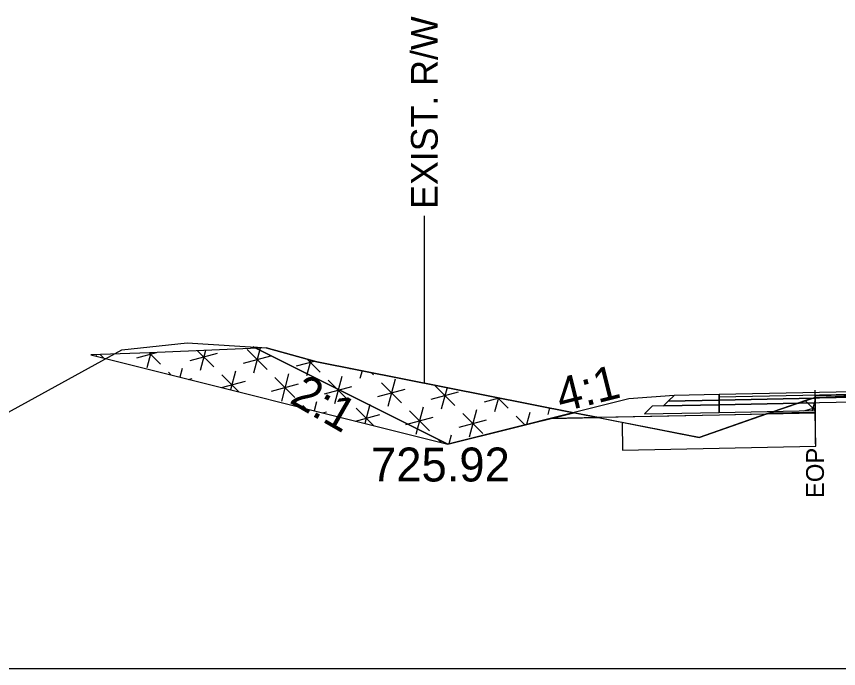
# Model space of a CAD drawing. Extents: x -26 to 4303, y -10 to 9577.
# Drawn here: x 4101.93 to 4138.27, y 2500 to 2528.83 of the extents above; entities that cross this region are included whole.
import ezdxf

# ---------------------------------------------------------------- set-up
doc = ezdxf.new("R2010")
doc.units = 0
for name, color, linetype in [('Exist CMT Pavement', 7, 'Continuous'), ('Old_Level_2', 7, 'Continuous'), ('Pattern 3', 7, 'Continuous'), ('Prop CMT Conc Surface', 7, 'Continuous'), ('Prop CMT Concrete Structures', 7, 'Continuous'), ('Prop CMT Pvmt Course 1', 7, 'Continuous'), ('Prop CMT Pvmt Course 2', 7, 'Continuous'), ('Prop CMT Pvmt Course 2 Wedge', 7, 'Continuous'), ('Prop CMT Pvmt Course 3', 7, 'Continuous'), ('Prop CMT Pvmt Surface', 7, 'Continuous'), ('Prop CMT Pvmt Surface Shoulder', 7, 'Continuous'), ('Prop CMT Pvmt Wedge Surface 1', 7, 'Continuous'), ('Prop CMT Pvmt Wedge Surface 2', 7, 'Continuous'), ('Prop CMT Shld Paved Course 1', 7, 'Continuous'), ('Prop CMT Shld Paved Course 2', 7, 'Continuous'), ('Prop CMT Shld Paved Course 3', 7, 'Continuous'), ('Prop CMT Slope Grass', 7, 'Continuous'), ('Prop CMT Subgrade Earthwork', 7, 'Continuous'), ('Prop Road Sect_ Recs - UC Shallow (Outline)', 7, 'Continuous'), ('Prop Shade Light', 7, 'Continuous'), ('Prop XS DDE Elevations', 7, 'Continuous'), ('Prop XS Ditch Standard Text', 7, 'Continuous'), ('Prop XS Hydro Elevations', 7, 'Continuous'), ('Prop XS Side Slope Text', 7, 'Continuous'), ('Prop XS Wedging', 7, 'Continuous')]:
    doc.layers.add(name, color=color, linetype=linetype)

msp = doc.modelspace()

# ---------------------------------------------------------------- linework, layer by layer
at = {"layer": 'Exist CMT Pavement'}
msp.add_lwpolyline([(4150, 2512.457), (4133, 2512.117)], dxfattribs=at)
at = {"layer": 'Old_Level_2'}
msp.add_line((4000, 2500), (4150, 2500), dxfattribs=at)
msp.add_line((4000, 2500), (4150, 2500), dxfattribs=at)
at = {"layer": 'Pattern 3'}
for p, q in [((4107.248, 2513.735), (4108.115, 2513.968)), ((4107.868, 2513.957), (4107.69, 2513.294)), ((4107.795, 2513.954), (4108.294, 2513.455)), ((4109.605, 2513.617), (4110.812, 2513.941)), ((4109.939, 2514.048), (4110.65, 2513.337)), ((4110.285, 2514.064), (4110.047, 2513.175)), ((4112.123, 2514.102), (4113.007, 2513.218)), ((4112.702, 2514.171), (4112.403, 2513.057)), ((4105.457, 2513.872), (4105.44, 2513.807)), ((4105.633, 2513.878), (4105.792, 2513.719)), ((4111.961, 2513.499), (4113.169, 2513.822)), ((4114.318, 2513.38), (4115.102, 2513.59)), ((4114.946, 2513.634), (4114.76, 2512.938)), ((4114.785, 2513.678), (4115.363, 2513.1)), ((4109.251, 2513.263), (4109.148, 2512.88)), ((4116.674, 2513.262), (4116.692, 2513.267)), ((4108.647, 2513.102), (4108.776, 2512.973)), ((4111.004, 2512.983), (4111.76, 2512.227)), ((4111.608, 2513.145), (4111.387, 2512.32)), ((4113.36, 2512.865), (4114.244, 2511.981)), ((4113.964, 2513.027), (4113.641, 2511.819)), ((4116.321, 2512.908), (4115.997, 2511.701)), ((4117.208, 2513.164), (4117.116, 2512.82)), ((4117.618, 2513.083), (4117.72, 2512.982)), ((4109.543, 2512.781), (4109.693, 2512.822)), ((4110.99, 2512.419), (4112.05, 2512.703)), ((4113.199, 2512.261), (4114.406, 2512.585)), ((4115.717, 2512.746), (4116.601, 2511.863)), ((4118.073, 2512.628), (4118.957, 2511.744)), ((4118.677, 2512.79), (4118.353, 2511.582)), ((4119.476, 2512.715), (4119.472, 2512.701)), ((4120.43, 2512.51), (4121.314, 2511.626)), ((4115.555, 2512.143), (4116.762, 2512.466)), ((4117.911, 2512.024), (4119.119, 2512.348)), ((4120.268, 2511.906), (4121.475, 2512.229)), ((4120.966, 2512.42), (4120.71, 2511.464)), ((4115.201, 2511.789), (4115.095, 2511.393)), ((4122.624, 2511.788), (4123.276, 2511.962)), ((4123.234, 2511.97), (4123.066, 2511.346)), ((4123.201, 2511.977), (4123.67, 2511.507)), ((4136.8, 2511.844), (4137.234, 2511.41)), ((4137.219, 2511.819), (4137.109, 2511.408)), ((4114.598, 2511.627), (4114.744, 2511.481)), ((4116.954, 2511.509), (4117.728, 2510.735)), ((4117.558, 2511.671), (4117.334, 2510.834)), ((4119.311, 2511.391), (4120.195, 2510.507)), ((4119.914, 2511.552), (4119.591, 2510.345)), ((4122.271, 2511.434), (4121.947, 2510.227)), ((4125.501, 2511.521), (4125.423, 2511.227)), ((4125.992, 2511.424), (4126.027, 2511.389)), ((4136.733, 2511.4), (4137.229, 2511.533)), ((4115.467, 2511.3), (4115.643, 2511.347)), ((4116.915, 2510.938), (4118, 2511.229)), ((4119.149, 2510.787), (4120.356, 2511.11)), ((4121.667, 2511.272), (4122.551, 2510.388)), ((4124.024, 2511.154), (4124.408, 2510.769)), ((4124.627, 2511.316), (4124.486, 2510.788)), ((4121.505, 2510.669), (4122.713, 2510.992)), ((4121.152, 2510.315), (4121.048, 2509.929)), ((4120.548, 2510.153), (4120.713, 2509.989))]:
    msp.add_line(p, q, dxfattribs=at)
for points in [[(4105.215, 2513.863), (4121, 2509.917), (4126.569, 2511.309), (4115.209, 2513.561), (4112.966, 2514.182), (4107.811, 2513.954)], [(4135.17, 2511.285), (4137.235, 2511.986), (4137.234, 2511.327)]]:
    msp.add_lwpolyline(points, close=True, dxfattribs=at)
at = {"layer": 'Prop CMT Conc Surface'}
for points in [[(4137.234, 2511.952), (4133, 2511.867)], [(4133, 2511.867), (4133, 2511.659)], [(4133, 2511.659), (4137.234, 2511.743)], [(4137.234, 2511.743), (4137.234, 2511.952)]]:
    msp.add_lwpolyline(points, dxfattribs=at)
at = {"layer": 'Prop CMT Concrete Structures'}
for points in [[(4133, 2511.867), (4133, 2512.117)], [(4150, 2512.332), (4137.234, 2512.077)], [(4137.234, 2511.952), (4133, 2511.867)], [(4137.234, 2512.077), (4137.234, 2511.952)]]:
    msp.add_lwpolyline(points, dxfattribs=at)
at = {"layer": 'Prop CMT Pvmt Course 1'}
for points in [[(4137.234, 2511.743), (4133, 2511.659)], [(4137.234, 2511.41), (4137.234, 2511.743)], [(4133, 2511.659), (4133, 2511.325)], [(4133, 2511.325), (4137.234, 2511.41)]]:
    msp.add_lwpolyline(points, dxfattribs=at)
at = {"layer": 'Prop CMT Pvmt Course 2'}
for points in [[(4133, 2512.117), (4131, 2512.077), (4130.745, 2511.822)], [(4133, 2511.867), (4133, 2512.117)], [(4130.745, 2511.822), (4133, 2511.867)]]:
    msp.add_lwpolyline(points, dxfattribs=at)
at = {"layer": 'Prop CMT Pvmt Course 2 Wedge'}
msp.add_line((4112.398, 2514.218), (4121, 2509.917), dxfattribs=at)
msp.add_lwpolyline([(4131, 2512.077), (4129, 2511.917), (4121, 2509.917)], dxfattribs=at)
at = {"layer": 'Prop CMT Pvmt Course 3'}
for points in [[(4133, 2511.867), (4130.745, 2511.822), (4130.532, 2511.609)], [(4133, 2511.659), (4133, 2511.867)], [(4130.532, 2511.609), (4133, 2511.659)]]:
    msp.add_lwpolyline(points, dxfattribs=at)
at = {"layer": 'Prop CMT Pvmt Surface'}
for points in [[(4150, 2512.207), (4133, 2511.867)], [(4133, 2511.867), (4133, 2512.117)]]:
    msp.add_lwpolyline(points, dxfattribs=at)
at = {"layer": 'Prop CMT Pvmt Surface Shoulder'}
msp.add_lwpolyline([(4137.235, 2511.986), (4137.247, 2511.988), (4137.261, 2511.989), (4137.334, 2511.99), (4138.91, 2512.042), (4139.904, 2512.044), (4140.165, 2512.046), (4141.331, 2512.06), (4142.666, 2512.082), (4143.763, 2512.091), (4145.167, 2512.103), (4146.195, 2512.099), (4147.668, 2512.094), (4148.11, 2512.09), (4149.998, 2512.087)], dxfattribs=at)
at = {"layer": 'Prop CMT Pvmt Wedge Surface 1'}
for p, q in [((4133.018, 2511.2), (4125.535, 2511.051)), ((4137.233, 2511.285), (4133.018, 2511.2))]:
    msp.add_line(p, q, dxfattribs=at)
msp.add_lwpolyline([(4137.233, 2511.285), (4137.235, 2511.986)], dxfattribs=at)
at = {"layer": 'Prop CMT Pvmt Wedge Surface 2'}
for points in [[(4137.234, 2512.077), (4137.247, 2512.077), (4137.261, 2512.077), (4137.334, 2512.079), (4138.91, 2512.11), (4139.904, 2512.13), (4140.165, 2512.135), (4141.331, 2512.159), (4142.666, 2512.185), (4143.763, 2512.207), (4145.167, 2512.235), (4146.195, 2512.256), (4147.668, 2512.285), (4148.11, 2512.294), (4150, 2512.332)], [(4150, 2512.207), (4148.11, 2512.169), (4147.668, 2512.16), (4146.195, 2512.131), (4145.167, 2512.11), (4144.545, 2512.098), (4143.763, 2512.091), (4142.666, 2512.082), (4141.331, 2512.06), (4140.165, 2512.046), (4139.904, 2512.044), (4138.91, 2512.042), (4137.334, 2511.99), (4137.261, 2511.989), (4137.247, 2511.988), (4137.234, 2511.986)], [(4137.234, 2511.986), (4137.234, 2512.077)]]:
    msp.add_lwpolyline(points, dxfattribs=at)
at = {"layer": 'Prop CMT Shld Paved Course 1'}
for points in [[(4133, 2511.659), (4133, 2512.117)], [(4150, 2511.999), (4133, 2511.659)]]:
    msp.add_lwpolyline(points, dxfattribs=at)
at = {"layer": 'Prop CMT Shld Paved Course 2'}
msp.add_lwpolyline([(4133, 2512.117), (4131, 2512.077)], dxfattribs=at)
at = {"layer": 'Prop CMT Shld Paved Course 3'}
for points in [[(4150, 2512.457), (4133, 2512.117)], [(4133, 2512.117), (4133, 2511.867)], [(4137.234, 2512.077), (4150, 2512.332)], [(4133, 2511.867), (4137.234, 2511.952)], [(4137.234, 2511.952), (4137.234, 2512.077)]]:
    msp.add_lwpolyline(points, dxfattribs=at)
at = {"layer": 'Prop CMT Slope Grass'}
msp.add_lwpolyline([(4089.451, 2504.678), (4106.586, 2514.091), (4109.473, 2514.401), (4112.966, 2514.182), (4115.209, 2513.561), (4132.115, 2510.21), (4136.865, 2511.882), (4137.214, 2511.984), (4138.91, 2512.042)], dxfattribs=at)
at = {"layer": 'Prop CMT Subgrade Earthwork'}
for points in [[(4133, 2511.659), (4130.532, 2511.609), (4130.032, 2511.599), (4129.692, 2511.259)], [(4133, 2511.325), (4133, 2511.659)], [(4129.692, 2511.259), (4133, 2511.325)]]:
    msp.add_lwpolyline(points, dxfattribs=at)
at = {"layer": 'Prop Road Sect_ Recs - UC Shallow (Outline)'}
msp.add_lwpolyline([(4128.722, 2509.656), (4137.264, 2509.827), (4137.234, 2511.327), (4135.17, 2511.285), (4134.794, 2511.153), (4132.115, 2510.21), (4128.714, 2510.884)], close=True, dxfattribs=at)
at = {"layer": 'Prop Shade Light'}
for p, q in [((4135.17, 2511.285), (4132.115, 2510.21)), ((4137.234, 2511.327), (4135.17, 2511.285)), ((4137.264, 2509.827), (4137.234, 2511.327)), ((4128.722, 2509.656), (4137.264, 2509.827))]:
    msp.add_line(p, q, dxfattribs=at)
msp.add_lwpolyline([(4132.115, 2510.21), (4128.714, 2510.884), (4128.722, 2509.656)], dxfattribs=at)
at = {"layer": 'Prop XS DDE Elevations'}
for points in [[(4125.535, 2511.051), (4121, 2509.917), (4112.398, 2514.218), (4112.966, 2514.182), (4115.209, 2513.561), (4126.569, 2511.309)], [(4137.214, 2511.984), (4137.235, 2511.986), (4137.233, 2511.285), (4135.044, 2511.241), (4136.865, 2511.882)], [(4137.235, 2511.986), (4137.261, 2511.989), (4137.334, 2511.99)], [(4126.569, 2511.309), (4125.535, 2511.051), (4127.659, 2511.093)], [(4132.115, 2510.21), (4135.044, 2511.241), (4133.018, 2511.2), (4127.659, 2511.093)]]:
    msp.add_lwpolyline(points, close=True, dxfattribs=at)
at = {"layer": 'Prop XS Ditch Standard Text'}
for p, q in [((4119.962, 2520.02), (4119.962, 2512.619)), ((4137.234, 2511.986), (4137.234, 2509.936))]:
    msp.add_line(p, q, dxfattribs=at)
at = {"layer": 'Prop XS Wedging'}
for p, q in [((4137.234, 2511.986), (4137.234, 2512.314)), ((4137.235, 2512.077), (4137.235, 2511.986))]:
    msp.add_line(p, q, dxfattribs=at)
for points in [[(4150.002, 2512.332), (4133.002, 2511.992)], [(4150, 2512.332), (4149.998, 2512.332), (4137.235, 2512.077)], [(4137.235, 2511.985), (4138.91, 2512.042), (4140.165, 2512.046), (4141.331, 2512.06), (4142.666, 2512.082), (4143.763, 2512.091), (4145.167, 2512.103), (4146.195, 2512.099), (4147.668, 2512.094), (4148.11, 2512.09), (4150.034, 2512.086), (4152.057, 2512.06), (4152.671, 2512.05), (4153.491, 2512.044), (4155.172, 2512.038), (4155.923, 2512.008), (4157.673, 2511.932), (4160.607, 2511.871), (4161.559, 2511.84), (4161.849, 2511.841)], [(4137.235, 2511.986), (4137.235, 2511.985)]]:
    msp.add_lwpolyline(points, dxfattribs=at)

# ---------------------------------------------------------------- texts
at = {"layer": 'Prop XS Ditch Standard Text'}
for s, height, p in [('EXIST. R/W', 1.1811, (4120.552, 2520.322)), ('EOP', 0.7874, (4137.627, 2507.538))]:
    msp.add_text(s, height=height, rotation=90, dxfattribs=at).set_placement(p)
at = {"layer": 'Prop XS Hydro Elevations'}
msp.add_text('725.92', height=1.5, dxfattribs=at).set_placement((4117.606, 2508.27))
at = {"layer": 'Prop XS Side Slope Text'}
for s, rotation, p in [('4:1', 14.0362, (4126.007, 2511.323)), ('2:1', 330.1407, (4113.948, 2511.777))]:
    msp.add_text(s, height=1.5, rotation=rotation, dxfattribs=at).set_placement(p)

doc.saveas('drawing.dxf')
